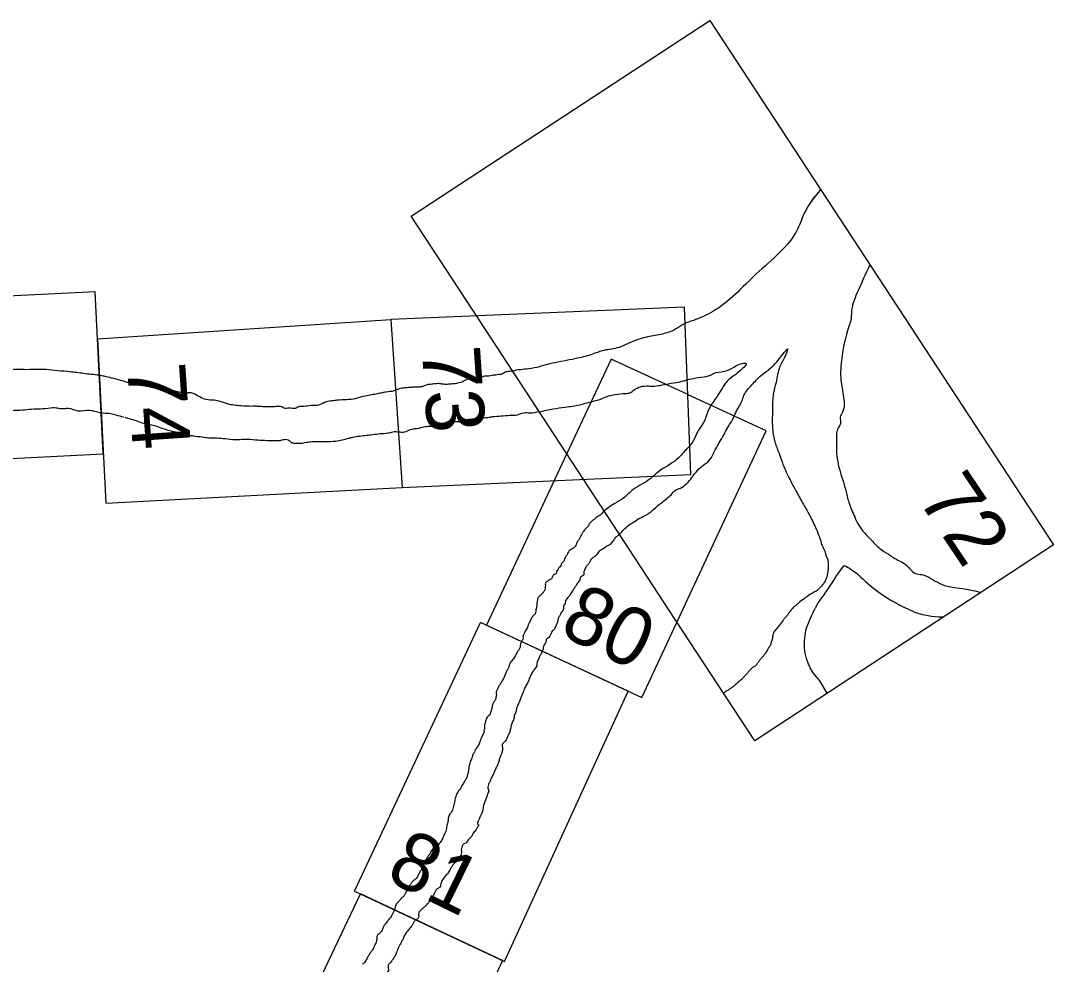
# Model space of a CAD drawing. Extents: x 3945642 to 3966284, y 206476 to 228921.
# Drawn here: x 3954111 to 3955150, y 211870 to 212819 of the extents above; entities that cross this region are included whole.
import ezdxf

# ---------------------------------------------------------------- set-up
doc = ezdxf.new("R2010")
doc.units = 0
doc.layers.add('V-ANNO-NPLT', color=7, linetype='Continuous')

msp = doc.modelspace()

# ---------------------------------------------------------------- linework, layer by layer
at = {"layer": 'V-ANNO-NPLT'}
for p, q in [((3954483.3, 212518.8), (3954495, 212349.7)), ((3954922.3, 212143.1), (3954914.7, 212155.4))]:
    msp.add_line(p, q, dxfattribs=at)
for points in [[(3954503.8, 212622.6), (3954804.3, 212819.3), (3955149.7, 212292), (3954849.4, 212095.1)], [(3954572.2, 212518.3), (3954503.8, 212622.6)], [(3954186, 212546.6), (3953908.9, 212532.8)], [(3954194.3, 212383.6), (3954186, 212546.6)], [(3953908.9, 212532.8), (3953889.6, 212368.4), (3954194.3, 212383.6)], [(3954483.3, 212518.8), (3954495, 212349.7), (3954785.2, 212363), (3954778.7, 212531.1)], [(3954778.7, 212531.1), (3954483.3, 212518.8)], [(3954188.4, 212499.3), (3954483.3, 212518.8)], [(3954770.1, 212216.2), (3954572.2, 212518.3)], [(3954188.4, 212499.3), (3954196.8, 212334.1), (3954495, 212349.7)], [(3954705, 212478.9), (3954660.5, 212384.1)], [(3954781.3, 212443.6), (3954705, 212478.9)], [(3954579.5, 212211.3), (3954735.8, 212138.7), (3954861, 212406.8), (3954781.9, 212443.4)], [(3954660.5, 212384.1), (3954579.5, 212211.3)], [(3954447, 211943.9), (3954573.7, 212214)], [(3954722.2, 212145), (3954573.7, 212214)], [(3954849.4, 212095.1), (3954770.1, 212216.2)], [(3954447, 211943.9), (3954597.9, 211873.3), (3954722.2, 212145)], [(3954470.5, 211602.2), (3954324.4, 211671), (3954453, 211941.1)], [(3954595.9, 211874.3), (3954453, 211941.1)], [(3954595.9, 211874.3), (3954470.5, 211602.2)]]:
    msp.add_lwpolyline(points, dxfattribs=at)
for points in [[(3954915.7, 212649.5), (3954900.3, 212627.8), (3954892.4, 212609.6), (3954851, 212564.6), (3954807.4, 212526.8), (3954787.8, 212517.6)], [(3954915.6, 212649.4), (3954900.3, 212627.8), (3954892.4, 212609.6), (3954851, 212564.6), (3954807.4, 212526.8), (3954787.8, 212517.6)], [(3954965.1, 212573.7), (3954952.2, 212545.1), (3954946.6, 212525.8), (3954946.3, 212519.7), (3954944.7, 212513.7), (3954936.1, 212472.3), (3954935.9, 212459.9), (3954938.3, 212443), (3954937.6, 212425.4), (3954935.4, 212420.5), (3954935.6, 212414.3), (3954933.2, 212409.7), (3954931.5, 212398.8), (3954932.2, 212379.2), (3954940.9, 212347), (3954944, 212334.9), (3954949.9, 212320.2), (3954954, 212311.8), (3954966.4, 212297.1), (3954977.1, 212287.1), (3954986, 212281.3), (3954990.4, 212278.4), (3955001.8, 212271.9), (3955011.1, 212263.4), (3955017.3, 212262.2), (3955035.4, 212253.3), (3955075.7, 212244.6), (3955076.8, 212244.2)], [(3954787.8, 212517.6), (3954778, 212514.2), (3954770.1, 212509.2), (3954758.4, 212504.6), (3954743.7, 212501.7), (3954727.5, 212497), (3954710.8, 212490.1), (3954696.1, 212487.3), (3954686.3, 212483.9), (3954671.3, 212479.8), (3954660.1, 212477.5), (3954648.6, 212475.2), (3954638.3, 212472.9), (3954632.9, 212471.3), (3954622.3, 212469.2), (3954613.7, 212468.3), (3954605.9, 212466.9)], [(3954713.4, 212302.5), (3954723, 212312.2), (3954727.6, 212315.1), (3954733.5, 212318.8), (3954741.1, 212322.7), (3954744.8, 212325.5), (3954748, 212328.1), (3954755.6, 212334.5), (3954765.2, 212342.5), (3954769.7, 212347.1), (3954774.7, 212349.3), (3954786.2, 212359.9), (3954790.4, 212365.3), (3954796.5, 212371.3), (3954803.3, 212376.5), (3954807.8, 212383.9), (3954810.3, 212388.8), (3954813.7, 212394.9), (3954818.5, 212403), (3954822.3, 212410.3), (3954826, 212415.8), (3954829.9, 212424.4), (3954833.8, 212431.3), (3954836.5, 212436.6), (3954838.6, 212442.6), (3954846.6, 212453.1), (3954856.1, 212462.7), (3954862.9, 212467.9), (3954871.5, 212476.1), (3954877.8, 212484), (3954882.4, 212489.1), (3954878.9, 212479.8), (3954874.4, 212470.8), (3954870.8, 212455.5), (3954868.1, 212443.8), (3954867.2, 212427.7), (3954867.5, 212406.8), (3954870.2, 212393.9), (3954874.4, 212382.8), (3954877.8, 212373.1), (3954884.9, 212357.4), (3954890.8, 212346.5), (3954897.6, 212334.3), (3954904, 212322.8), (3954910.5, 212309.5), (3954914.1, 212300.8), (3954915.8, 212295.8)], [(3954632.6, 212426), (3954646.8, 212428.8), (3954658.5, 212430.7), (3954673.6, 212432.9), (3954684.6, 212436.1), (3954694.6, 212438.8), (3954700.2, 212441.1), (3954709.2, 212443.3), (3954719.8, 212444.4), (3954723.9, 212445.1), (3954728.1, 212448), (3954734.4, 212451.1), (3954743, 212451.9), (3954748.6, 212451.8), (3954756.2, 212452.9), (3954768.5, 212455.1), (3954776.1, 212456.6), (3954785.9, 212459.2), (3954798.5, 212461.2), (3954806.9, 212463.7), (3954807.9, 212464.3), (3954818.9, 212466.7), (3954828.9, 212471.2), (3954835.2, 212474.2), (3954840.3, 212474.8), (3954831.9, 212464.9), (3954821.6, 212456.6), (3954811.5, 212441.3), (3954803.3, 212428.7), (3954798.4, 212416.3), (3954791.2, 212404.5), (3954786.9, 212395.4), (3954780, 212387.4), (3954771.2, 212378.2), (3954752.5, 212365.5), (3954744.2, 212358.5), (3954735.9, 212353.1), (3954727.1, 212347.7), (3954717.4, 212339.1), (3954708.8, 212333.8), (3954697.6, 212326)], [(3954190.2, 212462.7), (3954174.3, 212464.4), (3954160.7, 212466.1), (3954148.5, 212467.2), (3954136.7, 212468.5), (3954122.6, 212468.4), (3954112.2, 212468.4), (3954101.3, 212467.5), (3954097.9, 212465.9), (3954091.4, 212466.8), (3954087.5, 212467), (3954078.1, 212465.4), (3954066.9, 212462.3), (3954047.1, 212459)], [(3954343.6, 212431.4), (3954332.9, 212431.9), (3954325.7, 212432.6), (3954319.3, 212433.8), (3954310.7, 212436.7), (3954303.9, 212437.6), (3954295.9, 212438.7), (3954289.9, 212441.7), (3954282.7, 212444.9), (3954275.6, 212444.6), (3954265.3, 212447), (3954256.1, 212448.4), (3954248.3, 212450.8), (3954244, 212450.2), (3954238.1, 212452.2), (3954222.7, 212454.4), (3954211.9, 212457.5), (3954202.6, 212459.9), (3954195.3, 212461.6), (3954190.2, 212462.7)], [(3954605.9, 212466.9), (3954603.2, 212466.6), (3954599.7, 212466.1), (3954597.3, 212465.1), (3954595.5, 212463.9), (3954591.9, 212463.4), (3954589.2, 212462.9), (3954585.2, 212462.5), (3954582.1, 212461.9), (3954577.6, 212461.6), (3954574.4, 212460.5), (3954568.5, 212460.2), (3954565.2, 212459.4), (3954560.5, 212458.6), (3954556.3, 212456.4), (3954550.6, 212454.6), (3954545.5, 212453.9), (3954540.1, 212453.5), (3954535.7, 212453.7), (3954531.8, 212454.3), (3954527, 212453.9), (3954522.1, 212453.4), (3954518, 212452.5), (3954514.5, 212451.1), (3954510.4, 212450.7), (3954506.2, 212450.7), (3954502.2, 212450.3), (3954497.6, 212450), (3954491.8, 212448.9), (3954486.6, 212446.9), (3954478.7, 212445.8), (3954473.7, 212444.8), (3954468.8, 212443.8)], [(3954468.8, 212443.8), (3954462.7, 212442.6), (3954456.1, 212441.4), (3954447.6, 212439.1), (3954439.2, 212438.1), (3954429.3, 212437.5), (3954424.2, 212436.8), (3954418.7, 212436), (3954411.6, 212432.8), (3954403, 212432.1), (3954395.8, 212431.4), (3954391.2, 212431.1), (3954387.1, 212429.4), (3954381.4, 212429.6), (3954375.8, 212429.6), (3954373.7, 212430.9), (3954368, 212431.1), (3954362.4, 212431), (3954355.6, 212431), (3954350.6, 212431.3), (3954346.2, 212431.6), (3954343.6, 212431.4)], [(3954215, 212420.6), (3954207.3, 212422.4), (3954202, 212423.9), (3954194, 212424.4), (3954180.3, 212427.2), (3954169.1, 212426.7), (3954159.3, 212429.2), (3954151.8, 212428.9), (3954147, 212429.7), (3954143.7, 212429.8), (3954133.4, 212428.8), (3954124.3, 212428.5), (3954115, 212427.6), (3954106.5, 212427.1), (3954099.1, 212426.8), (3954092.6, 212424.9), (3954087.6, 212423.4), (3954084.9, 212425), (3954082.9, 212424.8), (3954079.7, 212422.8), (3954061, 212423.6)], [(3954365.4, 212396.7), (3954347.3, 212397.5), (3954336, 212398.1), (3954327, 212397.6), (3954317, 212398.6), (3954308.3, 212399.3), (3954300.3, 212399.5), (3954294.2, 212400.3), (3954283.9, 212401.6), (3954271.2, 212404.5), (3954255.8, 212408.3), (3954245.8, 212411.9), (3954235.2, 212414), (3954228.4, 212416.5), (3954219.4, 212419.1), (3954216.2, 212420.2)], [(3954632.6, 212426), (3954623.2, 212424.6), (3954617.2, 212424.7), (3954610.6, 212422.7), (3954602.9, 212422.1), (3954594.3, 212421.4), (3954585.7, 212420.8), (3954581, 212420), (3954572.1, 212419.1), (3954564.8, 212418.4), (3954558.5, 212417.4), (3954553.4, 212415.9), (3954548.4, 212415.8), (3954543.6, 212415.8), (3954539.9, 212415.6), (3954536.1, 212412.8), (3954531.5, 212412.5), (3954527.4, 212411.6), (3954523.3, 212411.2), (3954518, 212410.8), (3954511.6, 212409.3), (3954502.7, 212407.7), (3954497.2, 212405.5), (3954491.1, 212405.5)], [(3954406.3, 212395.9), (3954418.2, 212396.1), (3954427.8, 212396.5), (3954441.1, 212399.4)], [(3954491.1, 212405.5), (3954485.6, 212405.5), (3954480.3, 212404.3), (3954472.5, 212403.7), (3954465.4, 212402.7), (3954459, 212402), (3954452.2, 212401.2), (3954444.8, 212400), (3954441.2, 212399.4), (3954441.1, 212399.4)], [(3954406.3, 212395.9), (3954404.5, 212395.7), (3954398.5, 212394.9), (3954393, 212394), (3954387, 212394.1), (3954383.5, 212394.9), (3954380.6, 212397.4), (3954374.9, 212397.6), (3954370.7, 212396.7), (3954365.4, 212396.7)], [(3954697.6, 212326), (3954693.8, 212322), (3954691.4, 212320.5), (3954689.7, 212319.2), (3954688.4, 212317.8), (3954686.7, 212316.8), (3954685.3, 212315.5), (3954683.8, 212314.3), (3954682.5, 212312.4), (3954681.7, 212310.5), (3954679.7, 212308.7), (3954677.8, 212306.4), (3954676.6, 212304.8), (3954675.2, 212302.2), (3954674, 212300), (3954673.3, 212298.5), (3954671.5, 212296), (3954670.5, 212294), (3954667.8, 212289.4), (3954664.8, 212287.5), (3954662.9, 212286.3)], [(3954713.4, 212302.5), (3954711, 212300.7), (3954708.2, 212298), (3954707, 212296.1), (3954705.3, 212294.1), (3954704, 212292.4), (3954701.7, 212291.3), (3954699.6, 212290), (3954697.6, 212288.4), (3954694.5, 212286.8), (3954692.7, 212285.3), (3954691.4, 212283.6), (3954690.1, 212281.6), (3954687.2, 212279.5), (3954684.7, 212277.3), (3954683.3, 212274.4), (3954681.1, 212271.8), (3954679.1, 212268.8), (3954678.1, 212266.7), (3954677.5, 212263.9), (3954677.4, 212262.1), (3954675.7, 212260.7), (3954674.3, 212259.5), (3954673.7, 212257.7), (3954673, 212256), (3954671.7, 212254.3), (3954670.3, 212252.3), (3954668.6, 212249.7), (3954667.7, 212248), (3954666.1, 212245.8), (3954662.2, 212239.8), (3954659, 212235.4), (3954658.6, 212232.8), (3954657.5, 212231.2), (3954657.1, 212228.9)], [(3954915.8, 212295.8), (3954917.1, 212291.4), (3954919.8, 212285.8), (3954920.3, 212284.2), (3954921.3, 212280.7), (3954922.8, 212277.3), (3954923.2, 212272.8), (3954923.2, 212268.8), (3954922.8, 212264.5), (3954921.8, 212260.1), (3954920.6, 212256.6), (3954918.4, 212252.9), (3954914.4, 212248.6), (3954911.7, 212246), (3954907.5, 212243.6), (3954901.8, 212240), (3954899, 212238), (3954893.3, 212233.5), (3954890.8, 212231.3)], [(3954662.9, 212286.3), (3954661.6, 212284.2), (3954660.3, 212281.8), (3954658.7, 212279.1), (3954657.7, 212276.8)], [(3954657.7, 212276.8), (3954657.5, 212275.9), (3954656.7, 212274.9), (3954655.8, 212274.1), (3954654.8, 212272.6), (3954654.7, 212272.2), (3954654.4, 212270.9), (3954654.5, 212270.4), (3954653.4, 212270), (3954651.8, 212267.6), (3954650.5, 212265.6), (3954648.2, 212262.2), (3954647.1, 212262.1), (3954646.4, 212261.1), (3954645.6, 212259.2), (3954645, 212258), (3954644.4, 212257.6), (3954643, 212257)], [(3954939.1, 212271.5), (3954933.8, 212264.3), (3954929.8, 212258.3), (3954925.4, 212251.6), (3954920.9, 212244.9), (3954916.7, 212239), (3954913, 212233.7), (3954910.2, 212228.2)], [(3954939.1, 212271.5), (3954946.3, 212267.5), (3954965, 212251.6), (3955000.1, 212229.2), (3955010.1, 212224.6), (3955037.9, 212219.8), (3955038.2, 212219.8)], [(3954643, 212257), (3954641.6, 212256), (3954640.6, 212255.3), (3954639.1, 212254.1), (3954638.8, 212252.8), (3954638.9, 212250.9), (3954638.7, 212249.4), (3954638.6, 212248.2), (3954637.5, 212245.6), (3954636.7, 212244.2), (3954635.6, 212243.2), (3954634.2, 212241.8), (3954633.1, 212240.9), (3954632.2, 212239.7), (3954631.2, 212238.5), (3954630.8, 212237)], [(3954630.8, 212237), (3954630.4, 212233.9), (3954630.2, 212230.9), (3954629.4, 212226.7), (3954628.9, 212224.1), (3954628.7, 212223.1)], [(3954628.7, 212223.1), (3954628.7, 212222.8), (3954627.6, 212221.8), (3954626.7, 212221), (3954624.7, 212218), (3954623, 212214.4), (3954621.7, 212211.6), (3954620.9, 212209.2), (3954619.8, 212207.4), (3954617.5, 212203.1), (3954616.3, 212200.1), (3954616.3, 212197.4), (3954615, 212195.4), (3954614.2, 212193.2), (3954613.8, 212192.1), (3954613.5, 212189.4), (3954612.2, 212186.6), (3954610.6, 212184.2), (3954606.7, 212177.6), (3954603.5, 212173.6), (3954601.7, 212168.5), (3954600.2, 212165.6), (3954598.9, 212162.3), (3954595.8, 212156.1), (3954593.8, 212152.6), (3954592.1, 212149.9), (3954589.8, 212145.1), (3954589.3, 212143.7), (3954589.7, 212141.7), (3954588.9, 212138.9)], [(3954657.1, 212228.9), (3954655.9, 212225.2), (3954654.9, 212224), (3954654.2, 212222.3), (3954652.5, 212219.8), (3954651.8, 212218.1), (3954650.9, 212214.3), (3954648.4, 212208.3), (3954647.5, 212206.6), (3954645.6, 212205.4), (3954644.7, 212203), (3954643.2, 212200.3), (3954641.9, 212198.6), (3954640.1, 212197.2), (3954639.2, 212194.3), (3954638.3, 212192.5), (3954637.2, 212190.9), (3954636.5, 212187.2), (3954635.4, 212184.4), (3954634.5, 212182.4), (3954633, 212179.7), (3954632.3, 212178), (3954630.6, 212174), (3954629.8, 212169.7), (3954627.4, 212166.4), (3954625.2, 212162.9), (3954623, 212158.3), (3954621.8, 212155.1), (3954619.7, 212150.9), (3954617.6, 212147.2), (3954617, 212144.8)], [(3954890.8, 212231.3), (3954888.2, 212229.1), (3954885.1, 212225.6), (3954883, 212222.6), (3954881.4, 212220.5), (3954879.2, 212218.1), (3954876.1, 212213.6), (3954873.2, 212210), (3954869.9, 212206.1), (3954867.8, 212202.5), (3954867.1, 212198), (3954866, 212194), (3954864.7, 212190.6), (3954863, 212188), (3954862.4, 212186.6)], [(3954914.7, 212155.4), (3954908.3, 212163.4), (3954901.5, 212177.9), (3954899.5, 212188.3), (3954901.6, 212208.3), (3954910.2, 212228.2)], [(3954862.4, 212186.6), (3954860.2, 212183.3), (3954856.7, 212178.7), (3954854.4, 212176.1), (3954852.7, 212173.8), (3954850.8, 212171.2), (3954846, 212167.8), (3954842.4, 212163.6), (3954839.7, 212160.7), (3954837.5, 212158.1), (3954831, 212152.5), (3954827.1, 212149), (3954824.3, 212147.2)], [(3954617, 212144.8), (3954614.2, 212138.5), (3954612.7, 212134.7), (3954611.8, 212132.3), (3954609.9, 212127.9), (3954609.1, 212124.1), (3954607.6, 212120.2), (3954607.4, 212118.3), (3954605.6, 212113.6), (3954604.2, 212109.2), (3954603.3, 212105), (3954601.9, 212101.5), (3954600.3, 212098.4), (3954599, 212095.2), (3954597.7, 212094.1), (3954595.5, 212091), (3954595.6, 212088), (3954595.3, 212083.7), (3954594, 212080.6), (3954592.7, 212077.1), (3954591.8, 212073.3), (3954589.7, 212068.7), (3954587.8, 212064.5), (3954586.4, 212061.2), (3954584.2, 212057.2), (3954583, 212053.8), (3954581.5, 212051.1), (3954581.1, 212048.4)], [(3954824.3, 212147.2), (3954822, 212145.7), (3954820.5, 212144.7), (3954818.1, 212143)], [(3954585.5, 212130.7), (3954585.2, 212129), (3954584.6, 212126.9), (3954584, 212124.6), (3954583.5, 212122.3)], [(3954588.9, 212138.9), (3954588.8, 212136.5), (3954587.8, 212135.2), (3954586.3, 212132.8), (3954585.5, 212130.7)], [(3954583.5, 212122.3), (3954583.3, 212121.7), (3954582, 212120.4), (3954581.2, 212119.8), (3954579.7, 212118), (3954578.9, 212115.4), (3954578.4, 212113.4), (3954577.8, 212111.2), (3954577.7, 212109.4), (3954577.6, 212107.2), (3954577.1, 212105.1), (3954577.1, 212103.3), (3954576.2, 212101.9), (3954575.2, 212099.8), (3954574.4, 212098.1), (3954573.4, 212095.4), (3954572.7, 212092.9), (3954571.7, 212091.1), (3954570.9, 212089.6), (3954568.6, 212086.2), (3954567.5, 212083.7), (3954565.8, 212081.2)], [(3954565.8, 212081.2), (3954565, 212077.8), (3954563.8, 212075.5), (3954562.8, 212071.9), (3954562, 212068.7), (3954561.8, 212067.2)], [(3954561.8, 212067.2), (3954561.5, 212064.6), (3954560.6, 212060.9), (3954559.5, 212057.6), (3954558.6, 212055.7), (3954557.7, 212054.8)], [(3954557.7, 212054.9), (3954557.5, 212054.3), (3954555.1, 212050.4), (3954554.1, 212048.3), (3954550.8, 212043.5), (3954548.7, 212039.2), (3954547.7, 212034.7), (3954546.4, 212029.2), (3954544.8, 212024.2), (3954542.8, 212021.2), (3954541.2, 212017.2), (3954540.7, 212012.8), (3954539.8, 212009.5), (3954538.9, 212004.2), (3954537.2, 212000.7), (3954536.5, 211999.1), (3954535.7, 211997.4)], [(3954581.1, 212048.4), (3954581.3, 212046.5), (3954581.8, 212045.6), (3954580.6, 212041.3), (3954579.3, 212036.9), (3954576.8, 212030.3), (3954575.5, 212024.4), (3954572.2, 212016.4), (3954571, 212013.5), (3954570.5, 212012), (3954571, 212011.2), (3954571.5, 212010.9), (3954570.7, 212008.3), (3954568.9, 212005.1), (3954565.9, 212001.7), (3954564.3, 211998.6), (3954561.2, 211995.5), (3954558.8, 211992.2), (3954556.6, 211991.1), (3954554.8, 211988.2), (3954554.3, 211985.2), (3954554.5, 211982.6), (3954553.7, 211980), (3954551.2, 211976.4), (3954548.5, 211973.2), (3954545.8, 211970.3), (3954544.3, 211967.9), (3954543.5, 211966.8)], [(3954535.7, 211997.4), (3954533.8, 211993.8), (3954531.2, 211990.4), (3954529.3, 211988.3), (3954525.4, 211985.9), (3954522.9, 211981.9), (3954520.9, 211978.9), (3954519.7, 211976.9), (3954517.7, 211973.6), (3954515.5, 211968), (3954514, 211965.3), (3954512.2, 211962.4), (3954510.6, 211959.3), (3954508.2, 211956), (3954505.6, 211954), (3954503.5, 211951.2), (3954501.9, 211948.5), (3954500.2, 211945.6), (3954499, 211943.1), (3954497.6, 211940.7), (3954495.5, 211937.9), (3954493.8, 211936.8), (3954493.5, 211936.3)], [(3954543.5, 211966.8), (3954541.6, 211963), (3954538.9, 211959.8), (3954536, 211956.3), (3954534, 211952.3), (3954532.7, 211947.9), (3954530.2, 211946.1), (3954527.1, 211941.1), (3954525, 211937.7), (3954522.3, 211933.6), (3954520, 211931), (3954515.8, 211926.9), (3954513.4, 211924.5), (3954511.5, 211922.4), (3954511.3, 211919.9), (3954511.3, 211917.5), (3954510.1, 211916.1), (3954509.6, 211915.5)], [(3954493.5, 211936.3), (3954491.4, 211933.5), (3954488.9, 211930.8), (3954487.4, 211926.6), (3954485.2, 211921), (3954483.7, 211918.3), (3954481.2, 211915.2), (3954478.8, 211911.9), (3954476.5, 211908.9), (3954475.2, 211905.8), (3954474, 211903.8), (3954471.7, 211900.9), (3954469.9, 211899.5), (3954469.3, 211896.7), (3954468.7, 211892.8), (3954466.8, 211888.3), (3954465.3, 211885), (3954463.2, 211882.7), (3954461.3, 211879.5), (3954459.8, 211877.1)], [(3954509.6, 211915.5), (3954506.9, 211913.5), (3954506.2, 211911.9), (3954503.1, 211907.3), (3954500.1, 211903.6), (3954497.4, 211899.8), (3954495.7, 211895.8), (3954494.2, 211893), (3954491.5, 211887.8), (3954489.5, 211883), (3954488.3, 211879.8), (3954486.3, 211876.7), (3954484.3, 211873.7), (3954480.9, 211869.2), (3954480.8, 211866.5), (3954481.1, 211865.1), (3954479.3, 211861.3), (3954477.8, 211858.9), (3954475.3, 211857.3), (3954473.1, 211855.1), (3954471.8, 211851), (3954472.5, 211848.4), (3954472.8, 211847.1), (3954470.3, 211845.3), (3954468.8, 211844), (3954467.5, 211842.6), (3954466.7, 211841.5)], [(3954459.8, 211877.1), (3954459.3, 211875.8), (3954458.2, 211874.2), (3954456.8, 211872.1), (3954456.2, 211871.4), (3954454.9, 211870.3)]]:
    msp.add_spline(points, degree=3, dxfattribs=at)

# ---------------------------------------------------------------- texts
for s, rotation, p in [('73', 273.9412, (3954514.5, 212490.2)), ('74', 273.9412, (3954218.1, 212473.2)), ('72', 303.9412, (3955012.2, 212338.9)), ('80', 333.9412, (3954651.1, 212203.1)), ('81', 333.9412, (3954476.6, 211956.1))]:
    msp.add_text(s, height=58.5, rotation=rotation, dxfattribs=at).set_placement(p)

doc.saveas('drawing.dxf')
